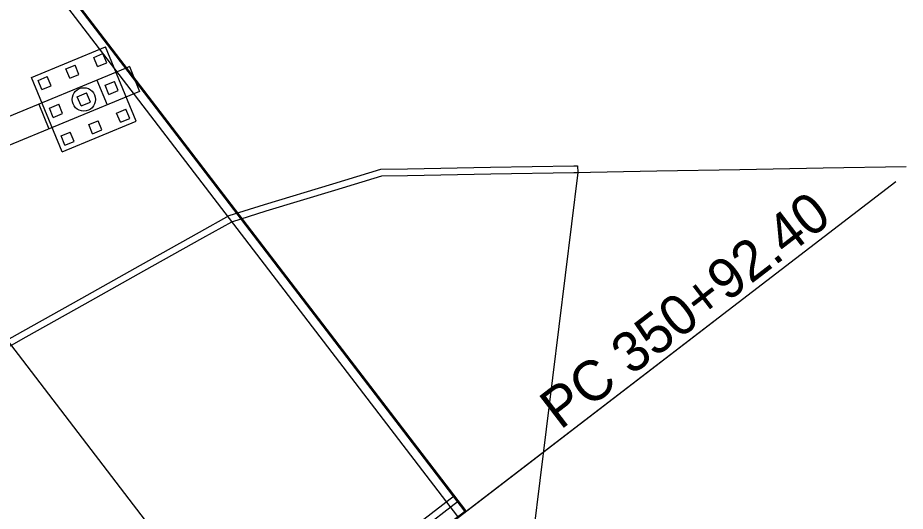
# Model space of a CAD drawing. Extents: x 881426 to 887360, y 1564404 to 1567430.
# Drawn here: x 884296.5 to 884429.3, y 1565221.7 to 1565295.5 of the extents above; entities that cross this region are included whole.
import ezdxf

# ---------------------------------------------------------------- set-up
doc = ezdxf.new("R2010")
doc.units = 0
for name, color, linetype in [('B_Concrete', 7, 'Continuous'), ('B_Concrete hidden', 7, 'Continuous'), ('R_Horz Alg', 7, 'Continuous'), ('R_Horz Alg Annot', 7, 'Continuous'), ('R_Proposed Const Limits_Hand', 7, 'Continuous')]:
    doc.layers.add(name, color=color, linetype=linetype)

msp = doc.modelspace()

# ---------------------------------------------------------------- linework, layer by layer
at = {"layer": 'B_Concrete'}
for p, q in [((884363.42, 1565221.74), (884072.18, 1565601.69)), ((884363.42, 1565221.74), (884072.18, 1565601.69)), ((884363.56, 1565221.85), (884072.31, 1565601.79)), ((884362.37, 1565220.93), (884071.12, 1565600.88)), ((884313.2, 1565288.23), (884312.8, 1565288.06)), ((884313.2, 1565288.23), (884313.81, 1565286.74)), ((884380.3, 1565272.42), (884372.61, 1565210.14)), ((884380.28, 1565273.42), (884380.3, 1565272.42)), ((884361.86, 1565224.06), (884299.95, 1565176.61)), ((884362.47, 1565223.27), (884300.56, 1565175.81))]:
    msp.add_line(p, q, dxfattribs=at)
for points in [[(884288.44, 1565243.73), (884297.26, 1565248.67), (884306.07, 1565253.61), (884314.88, 1565258.55), (884323.7, 1565263.49), (884328.11, 1565265.97), (884333.4, 1565267.62), (884343.63, 1565270.72), (884350.83, 1565272.89), (884354.82, 1565272.96), (884367.25, 1565273.19), (884379.69, 1565273.41), (884380.28, 1565273.42)], [(884288.93, 1565242.86), (884297.74, 1565247.8), (884306.56, 1565252.74), (884315.37, 1565257.68), (884324.19, 1565262.62), (884328.51, 1565265.04), (884333.69, 1565266.66), (884343.92, 1565269.76), (884350.99, 1565271.89), (884354.84, 1565271.96), (884367.27, 1565272.19), (884379.7, 1565272.41), (884380.3, 1565272.42)], [(884301.65, 1565174.39), (884363.56, 1565221.85)]]:
    msp.add_lwpolyline(points, dxfattribs=at)
at = {"layer": 'B_Concrete hidden'}
for p, q in [((884298.55, 1565286.59), (884309.64, 1565291.17)), ((884314.22, 1565280.07), (884309.64, 1565291.17)), ((884307.85, 1565289.61), (884309.23, 1565290.19)), ((884308.42, 1565288.23), (884307.85, 1565289.61)), ((884309.81, 1565288.8), (884309.23, 1565290.19)), ((884303.69, 1565287.9), (884305.07, 1565288.47)), ((884305.65, 1565287.08), (884305.07, 1565288.47)), ((884308.42, 1565288.23), (884309.81, 1565288.8)), ((884312.8, 1565288.06), (884238.7, 1565257.5)), ((884304.26, 1565286.51), (884303.69, 1565287.9)), ((884304.26, 1565286.51), (884305.65, 1565287.08)), ((884303.12, 1565275.5), (884298.55, 1565286.59)), ((884299.53, 1565286.18), (884300.91, 1565286.76)), ((884300.1, 1565284.8), (884299.53, 1565286.18)), ((884301.49, 1565285.37), (884300.91, 1565286.76)), ((884308.34, 1565286.22), (884309.87, 1565282.53)), ((884309.56, 1565285.45), (884310.95, 1565286.03)), ((884311.52, 1565284.64), (884310.95, 1565286.03)), ((884313.81, 1565286.74), (884314.72, 1565284.53)), ((884314.72, 1565284.53), (884240.64, 1565253.98)), ((884300.1, 1565284.8), (884301.49, 1565285.37)), ((884305.4, 1565283.74), (884306.79, 1565284.31)), ((884307.36, 1565282.92), (884306.79, 1565284.31)), ((884310.13, 1565284.07), (884309.56, 1565285.45)), ((884310.13, 1565284.07), (884311.52, 1565284.64)), ((884305.97, 1565282.35), (884305.4, 1565283.74)), ((884305.97, 1565282.35), (884307.36, 1565282.92)), ((884299.64, 1565282.63), (884301.16, 1565278.94)), ((884301.24, 1565282.02), (884302.63, 1565282.6)), ((884301.81, 1565280.64), (884301.24, 1565282.02)), ((884303.2, 1565281.21), (884302.63, 1565282.6)), ((884311.28, 1565281.29), (884312.67, 1565281.87)), ((884313.24, 1565280.48), (884312.67, 1565281.87)), ((884301.81, 1565280.64), (884303.2, 1565281.21)), ((884311.85, 1565279.91), (884311.28, 1565281.29)), ((884311.85, 1565279.91), (884313.24, 1565280.48)), ((884303.12, 1565275.5), (884314.22, 1565280.07)), ((884307.12, 1565279.58), (884308.51, 1565280.15)), ((884307.69, 1565278.19), (884307.12, 1565279.58)), ((884309.08, 1565278.76), (884308.51, 1565280.15)), ((884302.96, 1565277.86), (884304.34, 1565278.44)), ((884303.53, 1565276.48), (884302.96, 1565277.86)), ((884304.92, 1565277.05), (884304.34, 1565278.44)), ((884307.69, 1565278.19), (884309.08, 1565278.76)), ((884303.53, 1565276.48), (884304.92, 1565277.05))]:
    msp.add_line(p, q, dxfattribs=at)
msp.add_circle((884306.38, 1565283.33), 1.75, dxfattribs=at)
at = {"layer": 'R_Horz Alg'}
msp.add_line((883399.11, 1566415.89), (884332.67, 1565198.04), dxfattribs=at)
at = {"layer": 'R_Horz Alg Annot'}
msp.add_line((884332.67, 1565198.04), (884401.04, 1565250.45), dxfattribs=at)
msp.add_lwpolyline([(884332.67, 1565198.04), (884427.9, 1565271.04)], dxfattribs=at)
at = {"layer": 'R_Proposed Const Limits_Hand'}
msp.add_lwpolyline([(884288.93, 1565242.86), (884297.74, 1565247.8), (884306.56, 1565252.74), (884315.37, 1565257.68), (884324.19, 1565262.62), (884328.51, 1565265.04), (884333.69, 1565266.66), (884343.92, 1565269.76), (884350.99, 1565271.89), (884354.84, 1565271.96), (884367.27, 1565272.19), (884379.7, 1565272.41), (884392.14, 1565272.63), (884404.58, 1565272.85), (884417.01, 1565273.08), (884429.45, 1565273.3)], dxfattribs=at)

# ---------------------------------------------------------------- texts
at = {"layer": 'R_Horz Alg Annot'}
msp.add_text('PC 350+92.40', height=6, rotation=37.4722, dxfattribs=at).set_placement((884377.69, 1565233.81))

doc.saveas('drawing.dxf')
